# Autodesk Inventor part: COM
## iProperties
Created: 2008-01
Part Number: COM
Document SubType Name: Modeling
Designer: gstuder
Density: 1 g/cm^3
Author: gstuder
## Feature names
1. Extrusion1
2. Extrusion2
